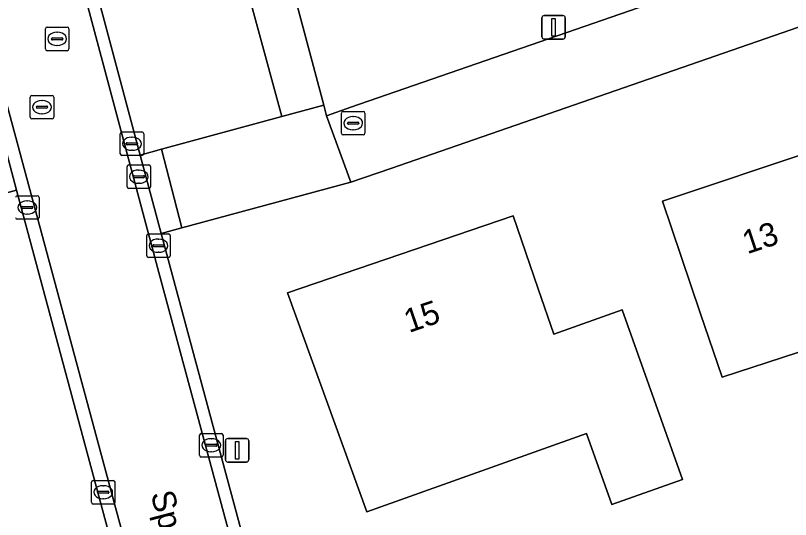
# Model space of a CAD drawing. Extents: x 162661 to 163484, y 380247 to 381230.
# Drawn here: x 162858.2 to 162891.15, y 380588.32 to 380609.74 of the extents above; entities that cross this region are included whole.
import ezdxf

# ---------------------------------------------------------------- set-up
doc = ezdxf.new("R2010")
doc.units = 0
for name, color, linetype in [('IMGEO_Erf', 7, 'Continuous'), ('IMGEO_Groenvoorziening', 7, 'Continuous'), ('IMGEO_Kolk', 7, 'Continuous'), ('IMGEO_Lichtmast', 7, 'Continuous'), ('IMGEO_Openbare_ruimte_label', 7, 'Continuous'), ('IMGEO_Pand', 7, 'Continuous'), ('IMGEO_Pand_nummerreeks', 7, 'Continuous'), ('IMGEO_Parkeervlak_open', 7, 'Continuous'), ('IMGEO_Rijbaan_lokaal_gesloten', 7, 'Continuous'), ('IMGEO_Rijbaan_lokaal_open', 7, 'Continuous'), ('IMGEO_Rioolput', 7, 'Continuous'), ('IMGEO_Voetpad_open', 7, 'Continuous')]:
    doc.layers.add(name, color=color, linetype=linetype)

msp = doc.modelspace()

# ---------------------------------------------------------------- linework, layer by layer
at = {"layer": 'IMGEO_Erf'}
for points in [[(162928.422, 380628.58), (162922.445, 380627.013), (162924.514, 380620.67), (162904.943, 380613.922), (162874.152, 380603.239), (162872.455, 380602.652), (162865.273, 380600.713), (162864.386, 380600.474), (162876.183, 380556.737), (162876.524, 380555.474), (162877.407, 380555.713), (162877.661, 380555.782), (162884.529, 380557.64), (162887.699, 380558.228), (162916.304, 380563.813), (162938.452, 380568.15), (162939.612, 380563.204), (162949.689, 380565.695)], [(162898.236, 380596.035), (162895.097, 380595.017), (162894.634, 380596.444), (162888.242, 380594.37), (162887.313, 380597.109), (162885.707, 380601.844), (162892.242, 380604.023), (162892.792, 380602.375), (162895.857, 380603.369), (162897.399, 380598.613)], [(162886.558, 380590.022), (162883.552, 380588.954), (162882.481, 380591.969), (162873.133, 380588.648), (162869.768, 380597.949), (162879.364, 380601.221), (162880.43, 380598.118), (162881.089, 380596.198), (162883.997, 380597.231)]]:
    msp.add_lwpolyline(points, close=True, dxfattribs=at)
at = {"layer": 'IMGEO_Groenvoorziening'}
msp.add_lwpolyline([(162917.172, 380627.95), (162868.058, 380618.39), (162867.984, 380618.376), (162868.09, 380617.967), (162871.308, 380605.93), (162871.429, 380605.476), (162872.456, 380605.847), (162905.704, 380617.341), (162918.864, 380621.921)], dxfattribs=at)
at = {"layer": 'IMGEO_Kolk'}
for p, q in [((162862.648, 380603.864), (162862.648, 380604.716)), ((162862.723, 380604.79), (162863.575, 380604.79)), ((162863.136, 380604.57), (162863.161, 380604.57)), ((162863.649, 380604.716), (162863.649, 380603.864)), ((162862.907, 380604.284), (162862.907, 380604.296)), ((162863.345, 380604.247), (162862.947, 380604.247)), ((162862.95, 380604.333), (162863.348, 380604.333)), ((162863.391, 380604.296), (162863.391, 380604.284)), ((162863.159, 380604.01), (162863.134, 380604.01)), ((162863.575, 380603.79), (162862.723, 380603.79)), ((162862.941, 380602.462), (162862.941, 380603.314)), ((162863.016, 380603.388), (162863.868, 380603.388)), ((162863.429, 380603.168), (162863.454, 380603.168)), ((162863.942, 380603.314), (162863.942, 380602.462)), ((162863.2, 380602.882), (162863.2, 380602.894)), ((162863.638, 380602.845), (162863.24, 380602.845)), ((162863.243, 380602.931), (162863.641, 380602.931)), ((162863.684, 380602.894), (162863.684, 380602.882)), ((162863.452, 380602.608), (162863.427, 380602.608)), ((162863.868, 380602.388), (162863.016, 380602.388)), ((162858.273, 380602.079), (162859.125, 380602.079)), ((162858.686, 380601.859), (162858.711, 380601.859)), ((162859.199, 380602.005), (162859.199, 380601.153)), ((162858.457, 380601.573), (162858.457, 380601.585)), ((162858.895, 380601.536), (162858.497, 380601.536)), ((162858.5, 380601.622), (162858.898, 380601.622)), ((162858.941, 380601.585), (162858.941, 380601.573)), ((162858.709, 380601.299), (162858.684, 380601.299)), ((162859.125, 380601.079), (162858.273, 380601.079)), ((162863.777, 380599.53), (162863.777, 380600.382)), ((162863.852, 380600.456), (162864.704, 380600.456)), ((162864.265, 380600.236), (162864.29, 380600.236)), ((162864.778, 380600.382), (162864.778, 380599.53)), ((162864.036, 380599.95), (162864.036, 380599.962)), ((162864.474, 380599.913), (162864.076, 380599.913)), ((162864.079, 380599.999), (162864.477, 380599.999)), ((162864.52, 380599.962), (162864.52, 380599.95)), ((162864.288, 380599.676), (162864.263, 380599.676)), ((162864.704, 380599.456), (162863.852, 380599.456)), ((162866.099, 380591.975), (162866.951, 380591.975)), ((162866.024, 380591.049), (162866.024, 380591.901)), ((162866.512, 380591.755), (162866.537, 380591.755)), ((162867.025, 380591.901), (162867.025, 380591.049)), ((162866.283, 380591.469), (162866.283, 380591.481)), ((162866.721, 380591.432), (162866.323, 380591.432)), ((162866.326, 380591.518), (162866.724, 380591.518)), ((162866.767, 380591.481), (162866.767, 380591.469)), ((162866.951, 380590.975), (162866.099, 380590.975)), ((162866.535, 380591.195), (162866.51, 380591.195)), ((162861.503, 380589.977), (162862.355, 380589.977)), ((162861.428, 380589.051), (162861.428, 380589.903)), ((162861.916, 380589.757), (162861.941, 380589.757)), ((162862.429, 380589.903), (162862.429, 380589.051)), ((162861.687, 380589.471), (162861.687, 380589.483)), ((162862.125, 380589.434), (162861.727, 380589.434)), ((162861.73, 380589.52), (162862.128, 380589.52)), ((162862.171, 380589.483), (162862.171, 380589.471)), ((162861.939, 380589.197), (162861.914, 380589.197)), ((162862.355, 380588.977), (162861.503, 380588.977))]:
    msp.add_line(p, q, dxfattribs=at)
for points in [[(162862.648, 380603.864), (162862.648, 380604.716)], [(162862.723, 380604.79), (162863.575, 380604.79)], [(162863.649, 380604.716), (162863.649, 380603.864)], [(162863.575, 380603.79), (162862.723, 380603.79)], [(162862.941, 380602.462), (162862.941, 380603.314)], [(162863.016, 380603.388), (162863.868, 380603.388)], [(162863.942, 380603.314), (162863.942, 380602.462)], [(162863.868, 380602.388), (162863.016, 380602.388)], [(162858.273, 380602.079), (162859.125, 380602.079)], [(162859.199, 380602.005), (162859.199, 380601.153)], [(162859.125, 380601.079), (162858.273, 380601.079)], [(162863.777, 380599.53), (162863.777, 380600.382)], [(162863.852, 380600.456), (162864.704, 380600.456)], [(162864.778, 380600.382), (162864.778, 380599.53)], [(162864.704, 380599.456), (162863.852, 380599.456)], [(162866.099, 380591.975), (162866.951, 380591.975)], [(162866.024, 380591.049), (162866.024, 380591.901)], [(162867.025, 380591.901), (162867.025, 380591.049)], [(162866.951, 380590.975), (162866.099, 380590.975)], [(162861.503, 380589.977), (162862.355, 380589.977)], [(162861.428, 380589.051), (162861.428, 380589.903)], [(162862.429, 380589.903), (162862.429, 380589.051)], [(162862.355, 380588.977), (162861.503, 380588.977)]]:
    msp.add_lwpolyline(points, dxfattribs=at)
for centre, radius, start, end in [((162862.725, 380604.714), 0.0765, 91.552, 178.448), ((162862.725, 380604.714), 0.0765, 91.552, 178.448), ((162863.573, 380604.714), 0.0765, 1.552, 88.448), ((162863.573, 380604.714), 0.0765, 1.552, 88.448), ((162862.947, 380604.293), 0.0403, 85.8775, 175.7526), ((162862.944, 380604.283), 0.0366, 178.938, 274.7102), ((162863.348, 380604.29), 0.043, 264.8664, 352.4533), ((162863.352, 380604.295), 0.0386, 1.7309, 96.639), ((162862.725, 380603.866), 0.0765, 181.552, 268.448), ((162862.725, 380603.866), 0.0765, 181.552, 268.448), ((162863.573, 380603.866), 0.0765, 271.552, 358.448), ((162863.573, 380603.866), 0.0765, 271.552, 358.448), ((162863.018, 380603.312), 0.0765, 91.552, 178.448), ((162863.018, 380603.312), 0.0765, 91.552, 178.448), ((162863.866, 380603.312), 0.0765, 1.552, 88.448), ((162863.866, 380603.312), 0.0765, 1.552, 88.448), ((162863.24, 380602.891), 0.0403, 85.8775, 175.7526), ((162863.237, 380602.881), 0.0366, 178.938, 274.7102), ((162863.641, 380602.888), 0.043, 264.8664, 352.4533), ((162863.645, 380602.893), 0.0386, 1.7309, 96.639), ((162863.018, 380602.464), 0.0765, 181.552, 268.448), ((162863.018, 380602.464), 0.0765, 181.552, 268.448), ((162863.866, 380602.464), 0.0765, 271.552, 358.448), ((162863.866, 380602.464), 0.0765, 271.552, 358.448), ((162858.275, 380602.003), 0.0765, 91.552, 178.448), ((162858.275, 380602.003), 0.0765, 91.552, 178.448), ((162859.123, 380602.003), 0.0765, 1.552, 88.448), ((162859.123, 380602.003), 0.0765, 1.552, 88.448), ((162858.497, 380601.582), 0.0403, 85.8775, 175.7526), ((162858.494, 380601.572), 0.0366, 178.938, 274.7102), ((162858.898, 380601.579), 0.043, 264.8664, 352.4533), ((162858.902, 380601.584), 0.0386, 1.7309, 96.639), ((162858.275, 380601.155), 0.0765, 181.552, 268.448), ((162858.275, 380601.155), 0.0765, 181.552, 268.448), ((162859.123, 380601.155), 0.0765, 271.552, 358.448), ((162859.123, 380601.155), 0.0765, 271.552, 358.448), ((162863.854, 380600.38), 0.0765, 91.552, 178.448), ((162863.854, 380600.38), 0.0765, 91.552, 178.448), ((162864.702, 380600.38), 0.0765, 1.552, 88.448), ((162864.702, 380600.38), 0.0765, 1.552, 88.448), ((162864.076, 380599.959), 0.0403, 85.8775, 175.7526), ((162864.073, 380599.949), 0.0366, 178.938, 274.7102), ((162864.477, 380599.956), 0.043, 264.8664, 352.4533), ((162864.481, 380599.961), 0.0386, 1.7309, 96.639), ((162863.854, 380599.532), 0.0765, 181.552, 268.448), ((162863.854, 380599.532), 0.0765, 181.552, 268.448), ((162864.702, 380599.532), 0.0765, 271.552, 358.448), ((162864.702, 380599.532), 0.0765, 271.552, 358.448), ((162866.101, 380591.899), 0.0765, 91.552, 178.448), ((162866.101, 380591.899), 0.0765, 91.552, 178.448), ((162866.949, 380591.899), 0.0765, 1.552, 88.448), ((162866.949, 380591.899), 0.0765, 1.552, 88.448), ((162866.323, 380591.478), 0.0403, 85.8775, 175.7526), ((162866.32, 380591.468), 0.0366, 178.938, 274.7102), ((162866.724, 380591.475), 0.043, 264.8664, 352.4533), ((162866.728, 380591.48), 0.0386, 1.7309, 96.639), ((162866.101, 380591.051), 0.0765, 181.552, 268.448), ((162866.101, 380591.051), 0.0765, 181.552, 268.448), ((162866.949, 380591.051), 0.0765, 271.552, 358.448), ((162866.949, 380591.051), 0.0765, 271.552, 358.448), ((162861.505, 380589.901), 0.0765, 91.552, 178.448), ((162861.505, 380589.901), 0.0765, 91.552, 178.448), ((162862.353, 380589.901), 0.0765, 1.552, 88.448), ((162862.353, 380589.901), 0.0765, 1.552, 88.448), ((162861.727, 380589.48), 0.0403, 85.8775, 175.7526), ((162861.724, 380589.47), 0.0366, 178.938, 274.7102), ((162862.128, 380589.477), 0.043, 264.8664, 352.4533), ((162862.132, 380589.482), 0.0386, 1.7309, 96.639), ((162861.505, 380589.053), 0.0765, 181.552, 268.448), ((162861.505, 380589.053), 0.0765, 181.552, 268.448), ((162862.353, 380589.053), 0.0765, 271.552, 358.448), ((162862.353, 380589.053), 0.0765, 271.552, 358.448)]:
    msp.add_arc(centre, radius, start, end, dxfattribs=at)
for centre, major_axis, ratio, start_param, end_param in [((162863.135, 380604.29), (-0.387, 0.002), 0.722429, 4.712389, 7.853982), ((162863.16, 380604.29), (-0.39, 0.002), 0.717154, 1.570796, 4.712389), ((162863.428, 380602.888), (-0.387, 0.002), 0.722429, 4.712389, 7.853982), ((162863.453, 380602.888), (-0.39, 0.002), 0.717154, 1.570796, 4.712389), ((162858.685, 380601.579), (-0.387, 0.002), 0.722429, 4.712389, 7.853982), ((162858.71, 380601.579), (-0.39, 0.002), 0.717154, 1.570796, 4.712389), ((162864.264, 380599.956), (-0.387, 0.002), 0.722429, 4.712389, 7.853982), ((162864.289, 380599.956), (-0.39, 0.002), 0.717154, 1.570796, 4.712389), ((162866.511, 380591.475), (-0.387, 0.002), 0.722429, 4.712389, 7.853982), ((162866.536, 380591.475), (-0.39, 0.002), 0.717154, 1.570796, 4.712389), ((162861.915, 380589.477), (-0.387, 0.002), 0.722429, 4.712389, 7.853982), ((162861.94, 380589.477), (-0.39, 0.002), 0.717154, 1.570796, 4.712389)]:
    msp.add_ellipse(centre, major_axis=major_axis, ratio=ratio, start_param=start_param, end_param=end_param, dxfattribs=at)
at = {"layer": 'IMGEO_Lichtmast'}
for p, q in [((162880.583, 380608.838), (162880.583, 380609.638)), ((162880.583, 380609.638), (162880.583, 380608.838)), ((162880.683, 380609.738), (162881.473, 380609.738)), ((162881.473, 380609.738), (162880.683, 380609.738)), ((162881.573, 380609.638), (162881.573, 380608.838)), ((162881.573, 380608.838), (162881.573, 380609.638)), ((162881.473, 380608.738), (162880.683, 380608.738)), ((162880.683, 380608.738), (162881.473, 380608.738)), ((162867.127, 380590.863), (162867.127, 380591.663)), ((162867.127, 380591.663), (162867.127, 380590.863)), ((162867.227, 380591.763), (162868.017, 380591.763)), ((162868.017, 380591.763), (162867.227, 380591.763)), ((162868.117, 380591.663), (162868.117, 380590.863)), ((162868.117, 380590.863), (162868.117, 380591.663)), ((162868.017, 380590.763), (162867.227, 380590.763)), ((162867.227, 380590.763), (162868.017, 380590.763))]:
    msp.add_line(p, q, dxfattribs=at)
for points in [[(162881.003, 380609.613), (162881.153, 380609.613), (162881.153, 380608.863), (162881.003, 380608.863), (162881.003, 380609.613)], [(162867.547, 380591.638), (162867.697, 380591.638), (162867.697, 380590.888), (162867.547, 380590.888), (162867.547, 380591.638)]]:
    msp.add_lwpolyline(points, dxfattribs=at)
for centre, start, end in [((162880.683, 380609.638), 90, 180), ((162880.683, 380609.638), 90, 180), ((162881.473, 380609.638), 0, 90), ((162881.473, 380609.638), 360, 90), ((162880.683, 380608.838), 180, 270), ((162880.683, 380608.838), 180, 270), ((162881.473, 380608.838), 270, 0), ((162881.473, 380608.838), 270, 0), ((162867.227, 380591.663), 90, 180), ((162867.227, 380591.663), 90, 180), ((162868.017, 380591.663), 0, 90), ((162868.017, 380591.663), 360, 90), ((162867.227, 380590.863), 180, 270), ((162867.227, 380590.863), 180, 270), ((162868.017, 380590.863), 270, 0), ((162868.017, 380590.863), 270, 0)]:
    msp.add_arc(centre, 0.1, start, end, dxfattribs=at)
at = {"layer": 'IMGEO_Pand'}
for points in [[(162895.857, 380603.369), (162892.792, 380602.375), (162892.242, 380604.023), (162885.707, 380601.844), (162887.313, 380597.109), (162888.242, 380594.37), (162894.634, 380596.444), (162895.097, 380595.017), (162898.236, 380596.035), (162897.399, 380598.613)], [(162869.768, 380597.949), (162873.133, 380588.648), (162882.481, 380591.969), (162883.552, 380588.954), (162886.558, 380590.022), (162883.997, 380597.231), (162881.089, 380596.198), (162880.43, 380598.118), (162879.364, 380601.221)]]:
    msp.add_lwpolyline(points, close=True, dxfattribs=at)
at = {"layer": 'IMGEO_Parkeervlak_open'}
for points in [[(162866.246, 380617.473), (162861.16, 380616.11), (162860.275, 380615.873), (162863.498, 380603.804), (162864.406, 380604.051), (162869.521, 380605.443)], [(162857.351, 380602.071), (162850.454, 380600.2), (162854.145, 380586.31), (162854.256, 380585.892), (162861.186, 380587.749), (162862.096, 380587.993), (162858.243, 380602.314)]]:
    msp.add_lwpolyline(points, close=True, dxfattribs=at)
at = {"layer": 'IMGEO_Rijbaan_lokaal_gesloten'}
msp.add_lwpolyline([(162889.085, 380501.285), (162890.125, 380503.167), (162886.907, 380515.067), (162864.293, 380598.811), (162858.479, 380620.583), (162847.107, 380663.14), (162842.816, 380661.994), (162845.2, 380653.071), (162853.834, 380620.756), (162875.558, 380540.207), (162882.977, 380512.698), (162884.78, 380511.647)], dxfattribs=at)
at = {"layer": 'IMGEO_Rijbaan_lokaal_open'}
for points in [[(162847.73, 380662.896), (162847.622, 380663.278), (162847.107, 380663.14), (162858.479, 380620.583), (162864.293, 380598.811), (162886.907, 380515.067), (162890.125, 380503.167)], [(162890.292, 380504.561), (162887.4, 380515.173), (162881.586, 380536.716), (162880.645, 380540.205), (162877.424, 380552.141), (162876.524, 380555.474), (162876.183, 380556.737), (162864.386, 380600.474), (162863.498, 380603.804), (162860.275, 380615.873), (162859.381, 380619.222), (162859.045, 380620.483), (162859.007, 380620.625), (162858.095, 380624.087), (162852.737, 380643.9), (162847.73, 380662.896)], [(162849.741, 380633.782), (162853.306, 380620.608), (162857.003, 380606.907), (162857.345, 380605.64), (162858.243, 380602.314), (162862.096, 380587.993), (162862.997, 380584.64), (162863.335, 380583.384), (162874.697, 380541.306), (162875.032, 380540.065), (162875.558, 380540.207), (162853.834, 380620.756), (162845.2, 380653.071)], [(162918.864, 380621.921), (162905.704, 380617.341), (162872.456, 380605.847), (162871.429, 380605.476), (162872.455, 380602.652), (162874.152, 380603.239), (162904.943, 380613.922), (162924.514, 380620.67), (162922.445, 380627.013)]]:
    msp.add_lwpolyline(points, dxfattribs=at)
msp.add_lwpolyline([(162871.429, 380605.476), (162871.308, 380605.93), (162869.521, 380605.443), (162864.406, 380604.051), (162865.273, 380600.713), (162872.455, 380602.652)], close=True, dxfattribs=at)
at = {"layer": 'IMGEO_Rioolput'}
for p, q in [((162859.47, 380608.317), (162859.47, 380609.169)), ((162859.545, 380609.243), (162860.397, 380609.243)), ((162860.471, 380609.169), (162860.471, 380608.317)), ((162859.772, 380608.786), (162860.17, 380608.786)), ((162859.958, 380609.023), (162859.983, 380609.023)), ((162859.729, 380608.737), (162859.729, 380608.749)), ((162860.167, 380608.7), (162859.769, 380608.7)), ((162859.981, 380608.463), (162859.956, 380608.463)), ((162860.213, 380608.749), (162860.213, 380608.737)), ((162860.397, 380608.243), (162859.545, 380608.243)), ((162858.824, 380605.417), (162858.824, 380606.269)), ((162858.899, 380606.343), (162859.751, 380606.343)), ((162859.312, 380606.123), (162859.337, 380606.123)), ((162859.825, 380606.269), (162859.825, 380605.417)), ((162859.083, 380605.837), (162859.083, 380605.849)), ((162859.521, 380605.8), (162859.123, 380605.8)), ((162859.126, 380605.886), (162859.524, 380605.886)), ((162859.567, 380605.849), (162859.567, 380605.837)), ((162859.335, 380605.563), (162859.31, 380605.563)), ((162872.058, 380604.735), (162872.058, 380605.587)), ((162872.133, 380605.661), (162872.985, 380605.661)), ((162873.059, 380605.587), (162873.059, 380604.735)), ((162859.751, 380605.343), (162858.899, 380605.343)), ((162872.317, 380605.155), (162872.317, 380605.167)), ((162872.36, 380605.204), (162872.758, 380605.204)), ((162872.546, 380605.441), (162872.571, 380605.441)), ((162872.801, 380605.167), (162872.801, 380605.155)), ((162872.755, 380605.118), (162872.357, 380605.118)), ((162872.569, 380604.881), (162872.544, 380604.881)), ((162872.985, 380604.661), (162872.133, 380604.661))]:
    msp.add_line(p, q, dxfattribs=at)
for points in [[(162859.47, 380608.317), (162859.47, 380609.169)], [(162859.545, 380609.243), (162860.397, 380609.243)], [(162860.471, 380609.169), (162860.471, 380608.317)], [(162860.397, 380608.243), (162859.545, 380608.243)], [(162858.824, 380605.417), (162858.824, 380606.269)], [(162858.899, 380606.343), (162859.751, 380606.343)], [(162859.825, 380606.269), (162859.825, 380605.417)], [(162872.058, 380604.735), (162872.058, 380605.587)], [(162872.133, 380605.661), (162872.985, 380605.661)], [(162873.059, 380605.587), (162873.059, 380604.735)], [(162859.751, 380605.343), (162858.899, 380605.343)], [(162872.985, 380604.661), (162872.133, 380604.661)]]:
    msp.add_lwpolyline(points, dxfattribs=at)
for centre, radius, start, end in [((162859.547, 380609.167), 0.0765, 91.552, 178.448), ((162859.547, 380609.167), 0.0765, 91.552, 178.448), ((162860.395, 380609.167), 0.0765, 1.552, 88.448), ((162860.395, 380609.167), 0.0765, 1.552, 88.448), ((162859.769, 380608.746), 0.0403, 85.8775, 175.7526), ((162860.174, 380608.748), 0.0386, 1.7309, 96.639), ((162859.766, 380608.736), 0.0366, 178.938, 274.7102), ((162860.17, 380608.743), 0.043, 264.8664, 352.4533), ((162859.547, 380608.319), 0.0765, 181.552, 268.448), ((162859.547, 380608.319), 0.0765, 181.552, 268.448), ((162860.395, 380608.319), 0.0765, 271.552, 358.448), ((162860.395, 380608.319), 0.0765, 271.552, 358.448), ((162858.901, 380606.267), 0.0765, 91.552, 178.448), ((162858.901, 380606.267), 0.0765, 91.552, 178.448), ((162859.749, 380606.267), 0.0765, 1.552, 88.448), ((162859.749, 380606.267), 0.0765, 1.552, 88.448), ((162859.123, 380605.846), 0.0403, 85.8775, 175.7526), ((162859.12, 380605.836), 0.0366, 178.938, 274.7102), ((162859.524, 380605.843), 0.043, 264.8664, 352.4533), ((162859.528, 380605.848), 0.0386, 1.7309, 96.639), ((162872.135, 380605.585), 0.0765, 91.552, 178.448), ((162872.135, 380605.585), 0.0765, 91.552, 178.448), ((162872.983, 380605.585), 0.0765, 1.552, 88.448), ((162872.983, 380605.585), 0.0765, 1.552, 88.448), ((162858.901, 380605.419), 0.0765, 181.552, 268.448), ((162858.901, 380605.419), 0.0765, 181.552, 268.448), ((162859.749, 380605.419), 0.0765, 271.552, 358.448), ((162859.749, 380605.419), 0.0765, 271.552, 358.448), ((162872.357, 380605.164), 0.0403, 85.8775, 175.7526), ((162872.354, 380605.154), 0.0366, 178.938, 274.7102), ((162872.758, 380605.161), 0.043, 264.8664, 352.4533), ((162872.762, 380605.166), 0.0386, 1.7309, 96.639), ((162872.135, 380604.737), 0.0765, 181.552, 268.448), ((162872.135, 380604.737), 0.0765, 181.552, 268.448), ((162872.983, 380604.737), 0.0765, 271.552, 358.448), ((162872.983, 380604.737), 0.0765, 271.552, 358.448)]:
    msp.add_arc(centre, radius, start, end, dxfattribs=at)
for centre, major_axis, ratio, start_param, end_param in [((162859.957, 380608.743), (-0.387, 0.002), 0.722429, 4.712389, 7.853982), ((162859.982, 380608.743), (-0.39, 0.002), 0.717154, 1.570796, 4.712389), ((162859.311, 380605.843), (-0.387, 0.002), 0.722429, 4.712389, 7.853982), ((162859.336, 380605.843), (-0.39, 0.002), 0.717154, 1.570796, 4.712389), ((162872.545, 380605.161), (-0.387, 0.002), 0.722429, 4.712389, 7.853982), ((162872.57, 380605.161), (-0.39, 0.002), 0.717154, 1.570796, 4.712389)]:
    msp.add_ellipse(centre, major_axis=major_axis, ratio=ratio, start_param=start_param, end_param=end_param, dxfattribs=at)
at = {"layer": 'IMGEO_Voetpad_open'}
for points in [[(162868.09, 380617.967), (162866.246, 380617.473), (162869.521, 380605.443), (162871.308, 380605.93)], [(162857.351, 380602.071), (162858.243, 380602.314), (162857.345, 380605.64), (162856.446, 380605.406)], [(162864.406, 380604.051), (162863.498, 380603.804), (162864.386, 380600.474), (162865.273, 380600.713)]]:
    msp.add_lwpolyline(points, close=True, dxfattribs=at)

# ---------------------------------------------------------------- texts
at = {"layer": 'IMGEO_Openbare_ruimte_label'}
msp.add_text('Sporkenhoutlaan', height=1, rotation=284.6619, dxfattribs=at).set_placement((162863.941, 380589.409))
at = {"layer": 'IMGEO_Pand_nummerreeks'}
for s, rotation, p in [('13', 18.4402, (162889.314, 380599.589)), ('15', 18.8281, (162874.929, 380596.243))]:
    msp.add_text(s, height=1, rotation=rotation, dxfattribs=at).set_placement(p)

doc.saveas('drawing.dxf')
